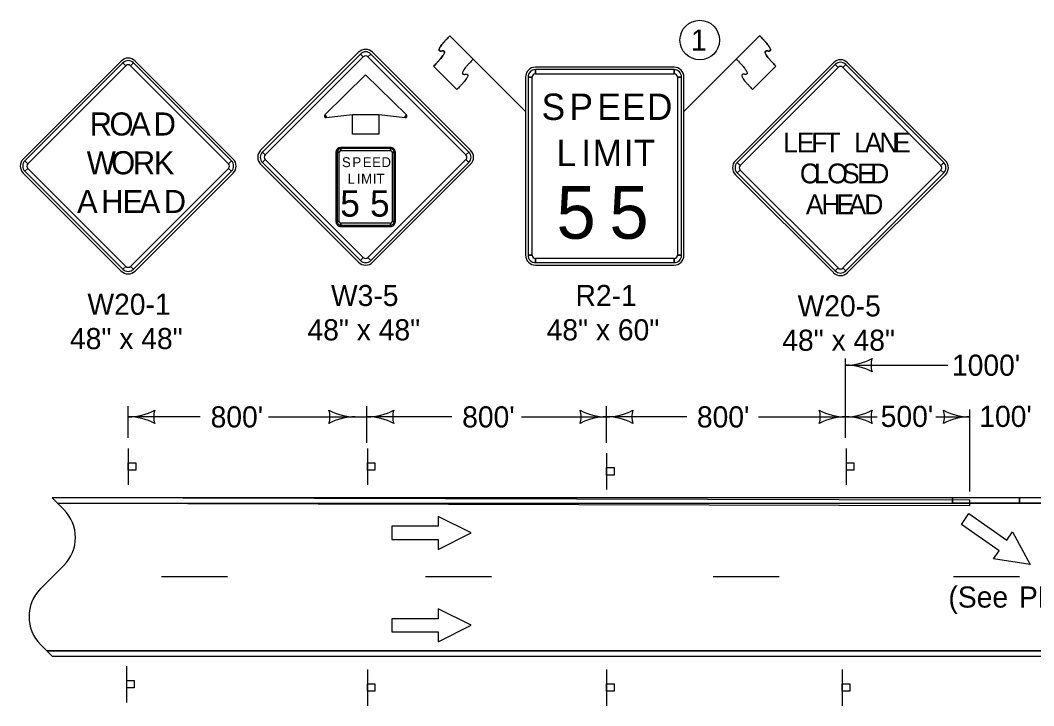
# Model space of a CAD drawing. Extents: x 10124 to 16850, y 7924 to 12166.
# Drawn here: x 10124 to 10892, y 9206 to 9725 of the extents above; entities that cross this region are included whole.
import ezdxf

# ---------------------------------------------------------------- set-up
doc = ezdxf.new("R2010")
doc.units = 0
for name, color, linetype in [('dsnShtPlotShapeBatchPrint', 7, 'Continuous'), ('dsnStdLabel', 7, 'Continuous'), ('dsnStdLineWork', 7, 'Continuous'), ('dsnStdShading', 7, 'Continuous'), ('SheetText', 7, 'Continuous')]:
    doc.layers.add(name, color=color, linetype=linetype)

msp = doc.modelspace()

# ---------------------------------------------------------------- linework, layer by layer
at = {"layer": 'dsnShtPlotShapeBatchPrint'}
msp.add_circle((10638.5, 9709.95), 15, dxfattribs=at)
at = {"layer": 'dsnStdLabel'}
for p, q in [((10506.56, 9655.86), (10449.24, 9713.18)), ((10449.24, 9713.18), (10466.92, 9695.49)), ((10626.56, 9655.86), (10683.88, 9713.18)), ((10683.88, 9713.18), (10666.19, 9695.49)), ((10380.08, 9700.71), (10305.83, 9626.46)), ((10381.4, 9699.38), (10383.61, 9697.17)), ((10387.15, 9697.17), (10389.36, 9699.38)), ((10464.93, 9626.46), (10390.68, 9700.71)), ((10200.17, 9694.05), (10125.92, 9619.81)), ((10201.5, 9692.73), (10203.71, 9690.52)), ((10207.24, 9690.52), (10209.45, 9692.73)), ((10285.02, 9619.81), (10210.78, 9694.05)), ((10436.86, 9690.19), (10454.54, 9672.51)), ((10454.54, 9672.51), (10436.86, 9690.19)), ((10739.8, 9692.8), (10665.55, 9618.55)), ((10696.25, 9690.19), (10678.58, 9672.51)), ((10678.58, 9672.51), (10696.25, 9690.19)), ((10741.12, 9691.47), (10743.33, 9689.26)), ((10746.87, 9689.26), (10749.08, 9691.47)), ((10824.65, 9618.55), (10750.4, 9692.8)), ((10506.56, 9681.91), (10506.56, 9546.91)), ((10508.43, 9681.91), (10511.56, 9681.91)), ((10619.06, 9689.41), (10514.06, 9689.41)), ((10514.06, 9684.41), (10514.06, 9687.54)), ((10619.06, 9687.54), (10619.06, 9684.41)), ((10621.56, 9681.91), (10624.68, 9681.91)), ((10626.56, 9546.91), (10626.56, 9681.91)), ((10355.38, 9652.41), (10354.5, 9653.29)), ((10355.54, 9651.17), (10355.38, 9652.41)), ((10415.38, 9652.41), (10415.22, 9651.17)), ((10416.26, 9653.29), (10415.38, 9652.41)), ((10404.13, 9628.66), (10366.63, 9628.66)), ((10309.37, 9622.92), (10307.16, 9625.13)), ((10362.88, 9624.91), (10362.88, 9572.41)), ((10363.82, 9624.91), (10365.38, 9624.91)), ((10366.63, 9626.16), (10366.63, 9627.72)), ((10404.13, 9627.72), (10404.13, 9626.16)), ((10405.38, 9624.91), (10406.94, 9624.91)), ((10407.88, 9572.41), (10407.88, 9624.91)), ((10463.6, 9625.13), (10461.39, 9622.92)), ((10129.46, 9616.27), (10127.25, 9618.48)), ((10283.7, 9618.48), (10281.49, 9616.27)), ((10305.83, 9615.85), (10380.08, 9541.61)), ((10307.16, 9617.18), (10309.37, 9619.39)), ((10390.68, 9541.61), (10464.93, 9615.85)), ((10461.39, 9619.39), (10463.6, 9617.18)), ((10669.09, 9615.02), (10666.88, 9617.23)), ((10823.32, 9617.23), (10821.12, 9615.02)), ((10125.92, 9609.2), (10200.17, 9534.96)), ((10127.25, 9610.53), (10129.46, 9612.74)), ((10210.78, 9534.96), (10285.02, 9609.2)), ((10281.49, 9612.74), (10283.7, 9610.53)), ((10665.55, 9607.95), (10739.8, 9533.7)), ((10666.88, 9609.27), (10669.09, 9611.48)), ((10750.4, 9533.7), (10824.65, 9607.95)), ((10821.12, 9611.48), (10823.32, 9609.27)), ((10365.38, 9572.41), (10363.82, 9572.41)), ((10366.63, 9569.59), (10366.63, 9571.16)), ((10366.63, 9568.66), (10404.13, 9568.66)), ((10404.13, 9571.16), (10404.13, 9569.59)), ((10406.94, 9572.41), (10405.38, 9572.41)), ((10383.61, 9545.14), (10381.4, 9542.93)), ((10389.36, 9542.93), (10387.15, 9545.14)), ((10511.56, 9546.91), (10508.43, 9546.91)), ((10514.06, 9541.29), (10514.06, 9544.41)), ((10619.06, 9544.41), (10619.06, 9541.29)), ((10624.68, 9546.91), (10621.56, 9546.91)), ((10203.71, 9538.49), (10201.5, 9536.28)), ((10209.45, 9536.28), (10207.24, 9538.49)), ((10514.06, 9539.41), (10619.06, 9539.41)), ((10743.33, 9537.24), (10741.12, 9535.03)), ((10749.08, 9535.03), (10746.87, 9537.24)), ((10204.27, 9235.57), (10204.27, 9208.07)), ((10386.67, 9233.04), (10386.67, 9205.54)), ((10567.85, 9233.04), (10567.85, 9205.54)), ((10746.39, 9233.04), (10746.39, 9205.54))]:
    msp.add_line(p, q, dxfattribs=at)
for points in [[(10381.4, 9699.38), (10307.16, 9625.13), (10309.37, 9622.92), (10383.61, 9697.17), (10381.4, 9699.38)], [(10463.6, 9625.13), (10389.36, 9699.38), (10387.15, 9697.17), (10461.39, 9622.92), (10463.6, 9625.13)], [(10201.5, 9692.73), (10127.25, 9618.48), (10129.46, 9616.27), (10203.71, 9690.52), (10201.5, 9692.73)], [(10283.7, 9618.48), (10209.45, 9692.73), (10207.24, 9690.52), (10281.49, 9616.27), (10283.7, 9618.48)], [(10741.12, 9691.47), (10666.88, 9617.23), (10669.09, 9615.02), (10743.33, 9689.26), (10741.12, 9691.47)], [(10823.32, 9617.23), (10749.08, 9691.47), (10746.87, 9689.26), (10821.12, 9615.02), (10823.32, 9617.23)], [(10385.38, 9683.66), (10354.5, 9653.29), (10355.38, 9652.41), (10355.54, 9651.17), (10375.38, 9653.66), (10395.38, 9653.66), (10415.22, 9651.17), (10415.38, 9652.41), (10416.26, 9653.29), (10385.38, 9683.66)], [(10508.43, 9681.91), (10508.43, 9546.91), (10511.56, 9546.91), (10511.56, 9681.91), (10508.43, 9681.91)], [(10619.06, 9687.54), (10514.06, 9687.54), (10514.06, 9684.41), (10619.06, 9684.41), (10619.06, 9687.54)], [(10624.68, 9546.91), (10624.68, 9681.91), (10621.56, 9681.91), (10621.56, 9546.91), (10624.68, 9546.91)], [(10395.38, 9638.66), (10375.38, 9638.66), (10375.38, 9653.66), (10395.38, 9653.66), (10395.38, 9638.66)], [(10363.82, 9624.91), (10363.82, 9572.41), (10365.38, 9572.41), (10365.38, 9624.91), (10363.82, 9624.91)], [(10404.13, 9627.72), (10366.63, 9627.72), (10366.63, 9626.16), (10404.13, 9626.16), (10404.13, 9627.72)], [(10406.94, 9572.41), (10406.94, 9624.91), (10405.38, 9624.91), (10405.38, 9572.41), (10406.94, 9572.41)], [(10307.16, 9617.18), (10381.4, 9542.93), (10383.61, 9545.14), (10309.37, 9619.39), (10307.16, 9617.18)], [(10389.36, 9542.93), (10463.6, 9617.18), (10461.39, 9619.39), (10387.15, 9545.14), (10389.36, 9542.93)], [(10127.25, 9610.53), (10201.5, 9536.28), (10203.71, 9538.49), (10129.46, 9612.74), (10127.25, 9610.53)], [(10209.45, 9536.28), (10283.7, 9610.53), (10281.49, 9612.74), (10207.24, 9538.49), (10209.45, 9536.28)], [(10666.88, 9609.27), (10741.12, 9535.03), (10743.33, 9537.24), (10669.09, 9611.48), (10666.88, 9609.27)], [(10749.08, 9535.03), (10823.32, 9609.27), (10821.12, 9611.48), (10746.87, 9537.24), (10749.08, 9535.03)], [(10366.63, 9569.59), (10404.13, 9569.59), (10404.13, 9571.16), (10366.63, 9571.16), (10366.63, 9569.59)], [(10514.06, 9541.29), (10619.06, 9541.29), (10619.06, 9544.41), (10514.06, 9544.41), (10514.06, 9541.29)], [(10204.36, 9219.12), (10204.36, 9224.75), (10209.99, 9224.75), (10209.99, 9219.12)], [(10386.76, 9216.59), (10386.76, 9222.22), (10392.39, 9222.22), (10392.39, 9216.59)], [(10567.94, 9216.59), (10567.94, 9222.22), (10573.57, 9222.22), (10573.57, 9216.59)], [(10746.49, 9216.59), (10746.49, 9222.22), (10752.11, 9222.22), (10752.11, 9216.59)]]:
    msp.add_lwpolyline(points, close=True, dxfattribs=at)
for centre, radius, start, end in [((10385.38, 9695.4), 7.5, 44.99999, 134.99974), ((10385.38, 9695.4), 5.62, 44.99999, 134.99974), ((10385.38, 9695.4), 2.5, 44.99999, 134.99974), ((10205.47, 9688.75), 7.5, 44.99999, 134.99974), ((10205.47, 9688.75), 5.62, 44.99999, 134.99974), ((10205.47, 9688.75), 2.5, 44.99999, 134.99974), ((10745.1, 9687.5), 7.5, 44.99999, 134.99974), ((10745.1, 9687.5), 5.62, 44.99999, 134.99974), ((10745.1, 9687.5), 2.5, 44.99999, 134.99974), ((10514.06, 9681.91), 7.5, 90.00021, 179.99985), ((10514.06, 9681.91), 5.62, 90.00021, 179.99985), ((10514.06, 9681.91), 2.5, 90.00021, 179.99985), ((10619.06, 9681.91), 7.5, 0, 90.00021), ((10619.06, 9681.91), 5.62, 0, 90.00021), ((10619.06, 9681.91), 2.5, 0, 90.00021), ((10355.38, 9652.41), 1.25, 134.99974, 277.15286), ((10415.38, 9652.41), 1.25, 262.84725, 44.9998), ((10366.63, 9624.91), 3.75, 90.00021, 179.99985), ((10404.13, 9624.91), 3.75, 0, 90.00021), ((10311.13, 9621.16), 7.5, 134.99974, 224.99995), ((10311.13, 9621.16), 5.62, 134.99974, 224.99995), ((10311.13, 9621.16), 2.5, 134.99974, 224.99995), ((10366.63, 9624.91), 2.81, 90.00021, 179.99985), ((10366.63, 9624.91), 1.25, 90.00021, 179.99985), ((10404.13, 9624.91), 2.81, 0, 90.00021), ((10404.13, 9624.91), 1.25, 0, 90.00021), ((10459.63, 9621.16), 2.5, 315.00016, 44.9998), ((10459.63, 9621.16), 5.62, 315.00016, 44.9998), ((10459.63, 9621.16), 7.5, 315.00016, 44.9998), ((10131.23, 9614.51), 7.5, 134.99974, 224.99995), ((10131.23, 9614.51), 5.62, 134.99974, 224.99995), ((10131.23, 9614.51), 2.5, 134.99974, 224.99995), ((10279.72, 9614.51), 2.5, 315.00016, 44.9998), ((10279.72, 9614.51), 5.62, 315.00016, 44.9998), ((10279.72, 9614.51), 7.5, 315.00016, 44.9998), ((10670.86, 9613.25), 7.5, 134.99974, 224.99995), ((10670.86, 9613.25), 5.62, 134.99974, 224.99995), ((10670.86, 9613.25), 2.5, 134.99974, 224.99995), ((10819.35, 9613.25), 2.5, 315.00016, 44.9998), ((10819.35, 9613.25), 5.62, 315.00016, 44.9998), ((10819.35, 9613.25), 7.5, 315.00016, 44.9998), ((10366.63, 9572.41), 3.75, 179.99985, 270.00006), ((10366.63, 9572.41), 2.81, 179.99985, 270.00006), ((10366.63, 9572.41), 1.25, 179.99985, 270.00006), ((10404.13, 9572.41), 3.75, 270.00006, 0.00027), ((10404.13, 9572.41), 2.81, 270.00006, 0.00027), ((10404.13, 9572.41), 1.25, 270.00006, 0.00027), ((10385.38, 9546.91), 2.5, 224.99995, 315.00016), ((10514.06, 9546.91), 7.5, 179.99985, 270.00006), ((10514.06, 9546.91), 5.62, 179.99985, 270.00006), ((10514.06, 9546.91), 2.5, 179.99985, 270.00006), ((10619.06, 9546.91), 7.5, 270.00006, 0.00027), ((10619.06, 9546.91), 5.62, 270.00006, 0.00027), ((10619.06, 9546.91), 2.5, 270.00006, 0.00027), ((10205.47, 9540.26), 5.62, 224.99995, 315.00016), ((10205.47, 9540.26), 2.5, 224.99995, 315.00016), ((10385.38, 9546.91), 7.5, 224.99995, 315.00016), ((10385.38, 9546.91), 5.62, 224.99995, 315.00016), ((10745.1, 9539), 2.5, 224.99995, 315.00016), ((10205.47, 9540.26), 7.5, 224.99995, 315.00016), ((10745.1, 9539), 7.5, 224.99995, 315.00016), ((10745.1, 9539), 5.62, 224.99995, 315.00016)]:
    msp.add_arc(centre, radius, start, end, dxfattribs=at)
for points in [[(10449.24, 9713.18), (10436.86, 9700.79), (10449.24, 9702.56), (10436.86, 9690.19)], [(10436.86, 9690.19), (10449.24, 9702.56), (10436.86, 9700.79), (10449.24, 9713.18)], [(10683.88, 9713.18), (10696.25, 9700.79), (10683.88, 9702.56), (10696.25, 9690.19)], [(10696.25, 9690.19), (10683.88, 9702.56), (10696.25, 9700.79), (10683.88, 9713.18)], [(10466.92, 9695.49), (10454.54, 9683.11), (10466.91, 9684.88), (10454.54, 9672.51)], [(10466.92, 9695.49), (10454.54, 9683.11), (10466.91, 9684.88), (10454.54, 9672.51)], [(10666.19, 9695.49), (10678.57, 9683.11), (10666.2, 9684.88), (10678.58, 9672.51)], [(10666.19, 9695.49), (10678.57, 9683.11), (10666.2, 9684.88), (10678.58, 9672.51)]]:
    msp.add_open_spline(points, degree=2, dxfattribs=at)
at = {"layer": 'dsnStdLineWork'}
for p, q in [((10156.71, 9354.24), (10147.93, 9363.02)), ((10151.91, 9359.04), (11348.15, 9359.04)), ((10836.72, 9342.96), (10842.45, 9351.16)), ((10842.45, 9351.16), (10871.12, 9331.09)), ((10865.38, 9322.89), (10836.72, 9342.96)), ((10871.12, 9331.09), (10875.42, 9337.23)), ((10875.42, 9337.23), (10888.73, 9312.65)), ((10861.08, 9316.75), (10865.38, 9322.89)), ((10888.73, 9312.65), (10861.08, 9316.75)), ((10139.15, 9294.25), (10156.71, 9311.82)), ((10147.93, 9243.04), (10139.15, 9251.83)), ((10143.95, 9247.02), (11762.1, 9247.02))]:
    msp.add_line(p, q, dxfattribs=at)
for points in [[(10230.76, 9303.44), (10280.75, 9303.44)], [(10430.73, 9303.44), (10480.72, 9303.44)], [(10648.7, 9303.44), (10698.69, 9303.44)], [(10830.67, 9303.44), (10880.66, 9303.44)]]:
    msp.add_lwpolyline(points, dxfattribs=at)
for centre, start, end in [((10135.51, 9333.03), 315, 45), ((10160.35, 9273.04), 135, 225)]:
    msp.add_arc(centre, 30, start, end, dxfattribs=at)
at = {"layer": 'dsnStdShading'}
for p, q in [((10829.93, 9363.04), (10147.93, 9363.04)), ((10147.93, 9363.04), (10156.72, 9354.24)), ((10843.14, 9361.34), (10147.93, 9363.04)), ((10829.93, 9359.04), (10829.93, 9363.04)), ((10880.75, 9363.04), (10829.93, 9363.04)), ((10829.93, 9363.04), (10829.93, 9359.04)), ((10843.14, 9357.34), (10843.14, 9361.34)), ((11072.72, 9363.04), (10880.75, 9363.04)), ((10880.75, 9363.04), (10880.75, 9359.04)), ((10880.75, 9359.04), (10880.75, 9363.04)), ((10151.92, 9359.04), (10843.14, 9357.34)), ((10829.93, 9359.04), (10880.75, 9359.04)), ((10880.75, 9359.04), (11072.72, 9359.04)), ((10156.72, 9311.82), (10139.14, 9294.25)), ((10139.14, 9251.83), (10143.93, 9247.04)), ((11527.46, 9247.04), (10143.93, 9247.04)), ((10143.93, 9247.04), (10147.93, 9243.04)), ((10143.93, 9247.04), (10978.7, 9247.04)), ((10147.93, 9243.04), (11554.23, 9243.04)), ((10147.93, 9243.04), (11525.74, 9243.04))]:
    msp.add_line(p, q, dxfattribs=at)
for points in [[(10147.93, 9363.04), (10151.92, 9359.05), (10151.92, 9359.04)], [(10978.7, 9359.04), (10880.75, 9359.04), (10829.93, 9359.04)], [(10143.93, 9247.04), (10143.93, 9247.04)], [(10143.93, 9247.04), (10143.93, 9247.04)]]:
    msp.add_lwpolyline(points, dxfattribs=at)
for centre, start, end in [((10135.51, 9333.03), 315, 45), ((10160.35, 9273.04), 135, 225)]:
    msp.add_arc(centre, 30, start, end, dxfattribs=at)
at = {"layer": 'SheetText'}
for p, q in [((10749.04, 9408.54), (10749.04, 9468.58)), ((10748.84, 9463.58), (10826.5, 9463.58)), ((10205.47, 9408.54), (10205.47, 9432.55)), ((10386.28, 9404.81), (10386.28, 9432.55)), ((10567.86, 9404.81), (10567.86, 9432.55)), ((10843.14, 9367.77), (10843.14, 9430.02)), ((10259.93, 9424.43), (10208.27, 9424.43)), ((10311.86, 9424.43), (10386.28, 9424.43)), ((10450.73, 9424.43), (10386.28, 9424.43)), ((10503.43, 9424.43), (10567.86, 9424.43)), ((10628.64, 9424.43), (10567.86, 9424.43)), ((10683.06, 9424.43), (10748.84, 9424.43)), ((10749.64, 9424.43), (10772.94, 9424.43)), ((10817.36, 9424.43), (10843.14, 9424.43)), ((10205.47, 9400.54), (10205.47, 9373.04)), ((10386.67, 9400.54), (10386.67, 9373.04)), ((10749.49, 9400.54), (10749.49, 9373.04)), ((10567.86, 9396.81), (10567.86, 9369.31))]:
    msp.add_line(p, q, dxfattribs=at)
for points in [[(10205.57, 9384.09), (10205.57, 9389.72), (10211.19, 9389.72), (10211.19, 9384.09)], [(10386.76, 9384.09), (10386.76, 9389.72), (10392.39, 9389.72), (10392.39, 9384.09)], [(10567.96, 9380.36), (10567.96, 9385.98), (10573.58, 9385.98), (10573.58, 9380.36)], [(10749.59, 9384.09), (10749.59, 9389.72), (10755.21, 9389.72), (10755.21, 9384.09)]]:
    msp.add_lwpolyline(points, close=True, dxfattribs=at)
for points in [[(10405.24, 9341.5), (10405.24, 9331.5), (10440.24, 9331.5), (10440.24, 9324), (10465.24, 9336.5), (10440.24, 9349), (10440.24, 9341.5), (10405.24, 9341.5)], [(10405.24, 9271.51), (10405.24, 9261.51), (10440.24, 9261.51), (10440.24, 9254.01), (10465.24, 9266.51), (10440.24, 9279.01), (10440.24, 9271.51), (10405.24, 9271.51)]]:
    msp.add_lwpolyline(points, dxfattribs=at)
for centre, radius, start, end in [((10749.04, 9506.08), 42.5, 270, 298.07249), ((10784.68, 9463.58), 16.42, 162.26665, 197.73335), ((10749.04, 9421.08), 42.5, 61.92751, 90), ((10205.58, 9466.93), 42.5, 270, 298.07249), ((10241.22, 9424.43), 16.42, 162.26665, 197.73335), ((10341.94, 9424.43), 16.42, 342.26665, 17.73335), ((10377.57, 9466.93), 42.5, 241.92751, 270), ((10386.67, 9466.93), 42.5, 270, 298.07249), ((10422.3, 9424.43), 16.42, 162.26665, 197.73335), ((10532.21, 9424.43), 16.42, 342.26665, 17.73335), ((10567.85, 9466.93), 42.5, 241.92751, 270), ((10567.85, 9466.93), 42.5, 270, 298.07249), ((10603.48, 9424.43), 16.42, 162.26665, 197.73335), ((10713.41, 9424.43), 16.42, 342.26665, 17.73335), ((10749.04, 9466.93), 42.5, 241.92751, 270), ((10749.04, 9466.93), 42.5, 270, 298.07249), ((10784.68, 9424.43), 16.42, 162.26665, 197.73335), ((10807.5, 9424.43), 16.42, 342.26665, 17.73335), ((10843.14, 9466.93), 42.5, 241.92751, 270), ((10205.58, 9381.93), 42.5, 61.92751, 90), ((10377.57, 9381.93), 42.5, 90, 118.07249), ((10386.67, 9381.93), 42.5, 61.92751, 90), ((10567.85, 9381.93), 42.5, 90, 118.07249), ((10567.85, 9381.93), 42.5, 61.92751, 90), ((10749.04, 9381.93), 42.5, 90, 118.07249), ((10749.04, 9381.93), 42.5, 61.92751, 90), ((10843.14, 9381.93), 42.5, 90, 118.07249)]:
    msp.add_arc(centre, radius, start, end, dxfattribs=at)

# ---------------------------------------------------------------- texts
at = {"layer": 'dsnShtPlotShapeBatchPrint'}
msp.add_text('1', height=16, dxfattribs=at).set_placement((10631.81, 9701.95))
at = {"layer": 'dsnStdLabel'}
for s, height, p in [('S', 20, (10518.68, 9649.41)), ('P', 20, (10539.78, 9649.41)), ('E', 20, (10560.87, 9649.41)), ('E', 20, (10579.68, 9649.41)), ('D', 20, (10598.49, 9649.41)), ('R', 17.5, (10176.31, 9637.63)), ('O', 17.5, (10191.32, 9637.63)), ('A', 17.5, (10206.87, 9637.63)), ('D', 17.5, (10224.75, 9637.63)), ('L', 15, (10701.57, 9624.81)), ('E', 15, (10712.02, 9624.81)), ('F', 15, (10722.93, 9624.81)), ('T', 15, (10732.86, 9624.81)), ('L', 15, (10755.36, 9624.81)), ('A', 15, (10763.47, 9624.81)), ('N', 15, (10774.64, 9624.81)), ('E', 15, (10785.09, 9624.81)), ('L', 20, (10529.93, 9614.41)), ('I', 20, (10548.74, 9614.41)), ('M', 20, (10557.34, 9614.41)), ('I', 20, (10580.93, 9614.41)), ('T', 20, (10588.49, 9614.41)), ('W', 17.5, (10174.03, 9608.26)), ('O', 17.5, (10192.62, 9608.26)), ('R', 17.5, (10209.03, 9608.26)), ('K', 17.5, (10224.89, 9608.26)), ('S', 7.5, (10367.43, 9613.66)), ('P', 7.5, (10375.34, 9613.66)), ('E', 7.5, (10383.25, 9613.66)), ('E', 7.5, (10390.3, 9613.66)), ('D', 7.5, (10397.36, 9613.66)), ('C', 15, (10714.32, 9601.38)), ('L', 15, (10725.05, 9601.38)), ('O', 15, (10735.08, 9601.38)), ('S', 15, (10746.29, 9601.38)), ('E', 15, (10757.65, 9601.38)), ('D', 15, (10767.68, 9601.38)), ('L', 7.5, (10371.65, 9601.16)), ('I', 7.5, (10378.7, 9601.16)), ('M', 7.5, (10381.92, 9601.16)), ('I', 7.5, (10390.77, 9601.16)), ('T', 7.5, (10393.61, 9601.16)), ('5', 40, (10529.93, 9559.41)), ('5', 40, (10570.05, 9559.41)), ('A', 17.5, (10166.75, 9578.88)), ('H', 17.5, (10184.96, 9578.88)), ('E', 17.5, (10201.19, 9578.88)), ('A', 17.5, (10214.23, 9578.88)), ('D', 17.5, (10232.44, 9578.88)), ('5', 20, (10366.13, 9576.16)), ('5', 20, (10388.69, 9576.16)), ('A', 15, (10718.86, 9577.94)), ('H', 15, (10730.74, 9577.94)), ('E', 15, (10742.07, 9577.94)), ('A', 15, (10751.26, 9577.94)), ('D', 15, (10763.14, 9577.94))]:
    msp.add_text(s, height=height, dxfattribs=at).set_placement(p)
at = {"layer": 'SheetText'}
for s, p in [('W3-5', (10359.13, 9508.41)), ('R2-1', (10544.39, 9508.41)), ('W20-1', (10174.62, 9501.76)), ('W20-5', (10712.64, 9500.51)), ('48" x 48"', (10341.31, 9482.41)), ('48" x 60"', (10522.49, 9482.41)), ('48" x 48"', (10161.41, 9475.76)), ('48" x 48"', (10701.03, 9474.51)), ("1000'", (10829.57, 9455.58)), ("800'", (10267.93, 9416.43)), ("800'", (10458.51, 9416.43)), ("800'", (10636.34, 9416.43)), ("500'", (10775.58, 9416.8)), ("100'", (10850.27, 9416.8)), ('(See ', (10826.92, 9279.91)), ('PM-111', (10880.33, 9279.91))]:
    msp.add_text(s, height=16, dxfattribs=at).set_placement(p)

doc.saveas('drawing.dxf')
